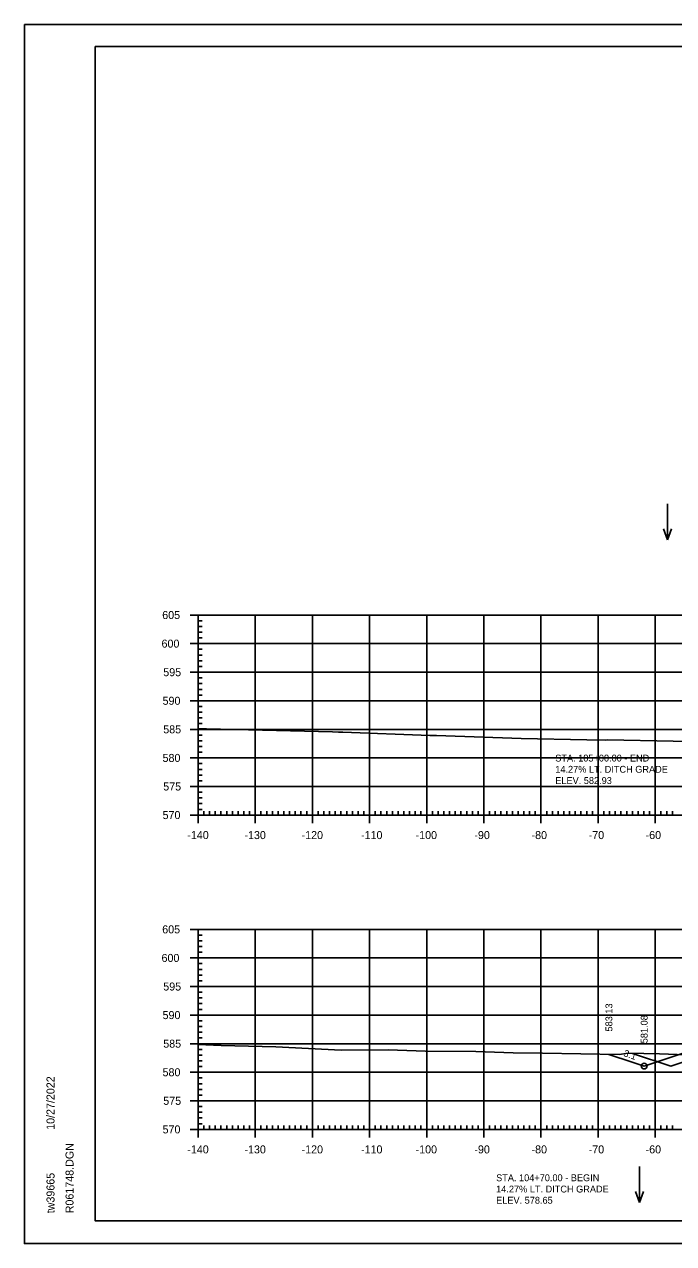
# Model space of a CAD drawing. Extents: x 961436 to 1372525, y 380079 to 2027791.
# Drawn here: x 1370020.1 to 1370133.7, y 380322.4 to 380535.8 of the extents above; entities that cross this region are included whole.
import ezdxf

# ---------------------------------------------------------------- set-up
doc = ezdxf.new("R2010")
doc.units = 0
for name, color, linetype in [('R_Axis', 7, 'Continuous'), ('R_Axis Annot', 7, 'Continuous'), ('R_Exist Surface', 7, 'Continuous'), ('R_Fin Surface', 7, 'Continuous'), ('R_Fin Surface Annot', 7, 'Continuous'), ('R_Grid', 7, 'Continuous'), ('R_No Plot', 7, 'Continuous'), ('R_Water Annot', 7, 'Continuous')]:
    doc.layers.add(name, color=color, linetype=linetype)

msp = doc.modelspace()

# ---------------------------------------------------------------- linework, layer by layer
at = {"layer": 'R_Axis'}
for p, q in [((1370049.1, 380432.4), (1370051.9, 380432.4)), ((1370050.5, 380397.4), (1370050.5, 380432.4)), ((1370050.5, 380431.4), (1370051.2, 380431.4)), ((1370050.5, 380430.4), (1370051.2, 380430.4)), ((1370050.5, 380429.4), (1370051.2, 380429.4)), ((1370050.5, 380428.4), (1370051.2, 380428.4)), ((1370049.1, 380427.4), (1370051.9, 380427.4)), ((1370050.5, 380426.4), (1370051.2, 380426.4)), ((1370050.5, 380425.4), (1370051.2, 380425.4)), ((1370050.5, 380424.4), (1370051.2, 380424.4)), ((1370049.1, 380422.4), (1370051.9, 380422.4)), ((1370050.5, 380423.4), (1370051.2, 380423.4)), ((1370050.5, 380421.4), (1370051.2, 380421.4)), ((1370050.5, 380420.4), (1370051.2, 380420.4)), ((1370050.5, 380419.4), (1370051.2, 380419.4)), ((1370049.1, 380417.4), (1370051.9, 380417.4)), ((1370050.5, 380418.4), (1370051.2, 380418.4)), ((1370050.5, 380416.4), (1370051.2, 380416.4)), ((1370050.5, 380415.4), (1370051.2, 380415.4)), ((1370050.5, 380414.4), (1370051.2, 380414.4)), ((1370050.5, 380413.4), (1370051.2, 380413.4)), ((1370049.1, 380412.4), (1370051.9, 380412.4)), ((1370050.5, 380411.4), (1370051.2, 380411.4)), ((1370050.5, 380410.4), (1370051.2, 380410.4)), ((1370050.5, 380409.4), (1370051.2, 380409.4)), ((1370049.1, 380407.4), (1370051.9, 380407.4)), ((1370050.5, 380408.4), (1370051.2, 380408.4)), ((1370050.5, 380406.4), (1370051.2, 380406.4)), ((1370050.5, 380405.4), (1370051.2, 380405.4)), ((1370049.1, 380402.4), (1370051.9, 380402.4)), ((1370050.5, 380404.4), (1370051.2, 380404.4)), ((1370050.5, 380403.4), (1370051.2, 380403.4)), ((1370050.5, 380401.4), (1370051.2, 380401.4)), ((1370050.5, 380400.4), (1370051.2, 380400.4)), ((1370050.5, 380399.4), (1370051.2, 380399.4)), ((1370050.5, 380396), (1370050.5, 380398.8)), ((1370050.5, 380398.4), (1370051.2, 380398.4)), ((1370051.5, 380397.4), (1370051.5, 380398.1)), ((1370052.5, 380397.4), (1370052.5, 380398.1)), ((1370053.5, 380397.4), (1370053.5, 380398.1)), ((1370054.5, 380397.4), (1370054.5, 380398.1)), ((1370055.5, 380397.4), (1370055.5, 380398.1)), ((1370056.5, 380397.4), (1370056.5, 380398.1)), ((1370057.5, 380397.4), (1370057.5, 380398.1)), ((1370058.5, 380397.4), (1370058.5, 380398.1)), ((1370059.5, 380397.4), (1370059.5, 380398.1)), ((1370060.5, 380396), (1370060.5, 380398.8)), ((1370061.5, 380397.4), (1370061.5, 380398.1)), ((1370062.5, 380397.4), (1370062.5, 380398.1)), ((1370063.5, 380397.4), (1370063.5, 380398.1)), ((1370064.5, 380397.4), (1370064.5, 380398.1)), ((1370065.5, 380397.4), (1370065.5, 380398.1)), ((1370066.5, 380397.4), (1370066.5, 380398.1)), ((1370067.5, 380397.4), (1370067.5, 380398.1)), ((1370068.5, 380397.4), (1370068.5, 380398.1)), ((1370069.5, 380397.4), (1370069.5, 380398.1)), ((1370070.5, 380396), (1370070.5, 380398.8)), ((1370071.5, 380397.4), (1370071.5, 380398.1)), ((1370072.5, 380397.4), (1370072.5, 380398.1)), ((1370073.5, 380397.4), (1370073.5, 380398.1)), ((1370074.5, 380397.4), (1370074.5, 380398.1)), ((1370075.5, 380397.4), (1370075.5, 380398.1)), ((1370076.5, 380397.4), (1370076.5, 380398.1)), ((1370077.5, 380397.4), (1370077.5, 380398.1)), ((1370078.5, 380397.4), (1370078.5, 380398.1)), ((1370079.5, 380397.4), (1370079.5, 380398.1)), ((1370080.5, 380396), (1370080.5, 380398.8)), ((1370081.5, 380397.4), (1370081.5, 380398.1)), ((1370082.5, 380397.4), (1370082.5, 380398.1)), ((1370083.5, 380397.4), (1370083.5, 380398.1)), ((1370084.5, 380397.4), (1370084.5, 380398.1)), ((1370085.5, 380397.4), (1370085.5, 380398.1)), ((1370086.5, 380397.4), (1370086.5, 380398.1)), ((1370087.5, 380397.4), (1370087.5, 380398.1)), ((1370088.5, 380397.4), (1370088.5, 380398.1)), ((1370089.5, 380397.4), (1370089.5, 380398.1)), ((1370090.5, 380396), (1370090.5, 380398.8)), ((1370091.5, 380397.4), (1370091.5, 380398.1)), ((1370092.5, 380397.4), (1370092.5, 380398.1)), ((1370093.5, 380397.4), (1370093.5, 380398.1)), ((1370094.5, 380397.4), (1370094.5, 380398.1)), ((1370095.5, 380397.4), (1370095.5, 380398.1)), ((1370096.5, 380397.4), (1370096.5, 380398.1)), ((1370097.5, 380397.4), (1370097.5, 380398.1)), ((1370098.5, 380397.4), (1370098.5, 380398.1)), ((1370099.5, 380397.4), (1370099.5, 380398.1)), ((1370100.5, 380396), (1370100.5, 380398.8)), ((1370101.5, 380397.4), (1370101.5, 380398.1)), ((1370102.5, 380397.4), (1370102.5, 380398.1)), ((1370103.5, 380397.4), (1370103.5, 380398.1)), ((1370104.5, 380397.4), (1370104.5, 380398.1)), ((1370105.5, 380397.4), (1370105.5, 380398.1)), ((1370106.5, 380397.4), (1370106.5, 380398.1)), ((1370107.5, 380397.4), (1370107.5, 380398.1)), ((1370108.5, 380397.4), (1370108.5, 380398.1)), ((1370109.5, 380397.4), (1370109.5, 380398.1)), ((1370110.5, 380396), (1370110.5, 380398.8)), ((1370111.5, 380397.4), (1370111.5, 380398.1)), ((1370112.5, 380397.4), (1370112.5, 380398.1)), ((1370113.5, 380397.4), (1370113.5, 380398.1)), ((1370114.5, 380397.4), (1370114.5, 380398.1)), ((1370115.5, 380397.4), (1370115.5, 380398.1)), ((1370116.5, 380397.4), (1370116.5, 380398.1)), ((1370117.5, 380397.4), (1370117.5, 380398.1)), ((1370118.5, 380397.4), (1370118.5, 380398.1)), ((1370119.5, 380397.4), (1370119.5, 380398.1)), ((1370120.5, 380396), (1370120.5, 380398.8)), ((1370121.5, 380397.4), (1370121.5, 380398.1)), ((1370122.5, 380397.4), (1370122.5, 380398.1)), ((1370123.5, 380397.4), (1370123.5, 380398.1)), ((1370124.5, 380397.4), (1370124.5, 380398.1)), ((1370125.5, 380397.4), (1370125.5, 380398.1)), ((1370126.5, 380397.4), (1370126.5, 380398.1)), ((1370127.5, 380397.4), (1370127.5, 380398.1)), ((1370128.5, 380397.4), (1370128.5, 380398.1)), ((1370129.5, 380397.4), (1370129.5, 380398.1)), ((1370130.5, 380396), (1370130.5, 380398.8)), ((1370131.5, 380397.4), (1370131.5, 380398.1)), ((1370132.5, 380397.4), (1370132.5, 380398.1)), ((1370133.5, 380397.4), (1370133.5, 380398.1)), ((1370049.1, 380397.4), (1370051.9, 380397.4)), ((1370050.5, 380397.4), (1370330.5, 380397.4)), ((1370049.1, 380377.4), (1370051.9, 380377.4)), ((1370050.5, 380342.4), (1370050.5, 380377.4)), ((1370050.5, 380376.4), (1370051.2, 380376.4)), ((1370050.5, 380375.4), (1370051.2, 380375.4)), ((1370050.5, 380374.4), (1370051.2, 380374.4)), ((1370050.5, 380373.4), (1370051.2, 380373.4)), ((1370049.1, 380372.4), (1370051.9, 380372.4)), ((1370050.5, 380371.4), (1370051.2, 380371.4)), ((1370050.5, 380370.4), (1370051.2, 380370.4)), ((1370050.5, 380369.4), (1370051.2, 380369.4)), ((1370050.5, 380368.4), (1370051.2, 380368.4)), ((1370049.1, 380367.4), (1370051.9, 380367.4)), ((1370050.5, 380366.4), (1370051.2, 380366.4)), ((1370050.5, 380365.4), (1370051.2, 380365.4)), ((1370050.5, 380364.4), (1370051.2, 380364.4)), ((1370049.1, 380362.4), (1370051.9, 380362.4)), ((1370050.5, 380363.4), (1370051.2, 380363.4)), ((1370050.5, 380361.4), (1370051.2, 380361.4)), ((1370050.5, 380360.4), (1370051.2, 380360.4)), ((1370050.5, 380359.4), (1370051.2, 380359.4)), ((1370050.5, 380358.4), (1370051.2, 380358.4)), ((1370049.1, 380357.4), (1370051.9, 380357.4)), ((1370050.5, 380356.4), (1370051.2, 380356.4)), ((1370050.5, 380355.4), (1370051.2, 380355.4)), ((1370050.5, 380354.4), (1370051.2, 380354.4)), ((1370050.5, 380353.4), (1370051.2, 380353.4)), ((1370049.1, 380352.4), (1370051.9, 380352.4)), ((1370050.5, 380351.4), (1370051.2, 380351.4)), ((1370050.5, 380350.4), (1370051.2, 380350.4)), ((1370050.5, 380349.4), (1370051.2, 380349.4)), ((1370049.1, 380347.4), (1370051.9, 380347.4)), ((1370050.5, 380348.4), (1370051.2, 380348.4)), ((1370050.5, 380346.4), (1370051.2, 380346.4)), ((1370050.5, 380345.4), (1370051.2, 380345.4)), ((1370050.5, 380344.4), (1370051.2, 380344.4)), ((1370050.5, 380341), (1370050.5, 380343.8)), ((1370050.5, 380343.4), (1370051.2, 380343.4)), ((1370051.5, 380342.4), (1370051.5, 380343.1)), ((1370052.5, 380342.4), (1370052.5, 380343.1)), ((1370053.5, 380342.4), (1370053.5, 380343.1)), ((1370054.5, 380342.4), (1370054.5, 380343.1)), ((1370055.5, 380342.4), (1370055.5, 380343.1)), ((1370056.5, 380342.4), (1370056.5, 380343.1)), ((1370057.5, 380342.4), (1370057.5, 380343.1)), ((1370058.5, 380342.4), (1370058.5, 380343.1)), ((1370059.5, 380342.4), (1370059.5, 380343.1)), ((1370060.5, 380341), (1370060.5, 380343.8)), ((1370061.5, 380342.4), (1370061.5, 380343.1)), ((1370062.5, 380342.4), (1370062.5, 380343.1)), ((1370063.5, 380342.4), (1370063.5, 380343.1)), ((1370064.5, 380342.4), (1370064.5, 380343.1)), ((1370065.5, 380342.4), (1370065.5, 380343.1)), ((1370066.5, 380342.4), (1370066.5, 380343.1)), ((1370067.5, 380342.4), (1370067.5, 380343.1)), ((1370068.5, 380342.4), (1370068.5, 380343.1)), ((1370069.5, 380342.4), (1370069.5, 380343.1)), ((1370070.5, 380341), (1370070.5, 380343.8)), ((1370071.5, 380342.4), (1370071.5, 380343.1)), ((1370072.5, 380342.4), (1370072.5, 380343.1)), ((1370073.5, 380342.4), (1370073.5, 380343.1)), ((1370074.5, 380342.4), (1370074.5, 380343.1)), ((1370075.5, 380342.4), (1370075.5, 380343.1)), ((1370076.5, 380342.4), (1370076.5, 380343.1)), ((1370077.5, 380342.4), (1370077.5, 380343.1)), ((1370078.5, 380342.4), (1370078.5, 380343.1)), ((1370079.5, 380342.4), (1370079.5, 380343.1)), ((1370080.5, 380341), (1370080.5, 380343.8)), ((1370081.5, 380342.4), (1370081.5, 380343.1)), ((1370082.5, 380342.4), (1370082.5, 380343.1)), ((1370083.5, 380342.4), (1370083.5, 380343.1)), ((1370084.5, 380342.4), (1370084.5, 380343.1)), ((1370085.5, 380342.4), (1370085.5, 380343.1)), ((1370086.5, 380342.4), (1370086.5, 380343.1)), ((1370087.5, 380342.4), (1370087.5, 380343.1)), ((1370088.5, 380342.4), (1370088.5, 380343.1)), ((1370089.5, 380342.4), (1370089.5, 380343.1)), ((1370090.5, 380341), (1370090.5, 380343.8)), ((1370091.5, 380342.4), (1370091.5, 380343.1)), ((1370092.5, 380342.4), (1370092.5, 380343.1)), ((1370093.5, 380342.4), (1370093.5, 380343.1)), ((1370094.5, 380342.4), (1370094.5, 380343.1)), ((1370095.5, 380342.4), (1370095.5, 380343.1)), ((1370096.5, 380342.4), (1370096.5, 380343.1)), ((1370097.5, 380342.4), (1370097.5, 380343.1)), ((1370098.5, 380342.4), (1370098.5, 380343.1)), ((1370099.5, 380342.4), (1370099.5, 380343.1)), ((1370100.5, 380341), (1370100.5, 380343.8)), ((1370101.5, 380342.4), (1370101.5, 380343.1)), ((1370102.5, 380342.4), (1370102.5, 380343.1)), ((1370103.5, 380342.4), (1370103.5, 380343.1)), ((1370104.5, 380342.4), (1370104.5, 380343.1)), ((1370105.5, 380342.4), (1370105.5, 380343.1)), ((1370106.5, 380342.4), (1370106.5, 380343.1)), ((1370107.5, 380342.4), (1370107.5, 380343.1)), ((1370108.5, 380342.4), (1370108.5, 380343.1)), ((1370109.5, 380342.4), (1370109.5, 380343.1)), ((1370110.5, 380341), (1370110.5, 380343.8)), ((1370111.5, 380342.4), (1370111.5, 380343.1)), ((1370112.5, 380342.4), (1370112.5, 380343.1)), ((1370113.5, 380342.4), (1370113.5, 380343.1)), ((1370114.5, 380342.4), (1370114.5, 380343.1)), ((1370115.5, 380342.4), (1370115.5, 380343.1)), ((1370116.5, 380342.4), (1370116.5, 380343.1)), ((1370117.5, 380342.4), (1370117.5, 380343.1)), ((1370118.5, 380342.4), (1370118.5, 380343.1)), ((1370119.5, 380342.4), (1370119.5, 380343.1)), ((1370120.5, 380341), (1370120.5, 380343.8)), ((1370121.5, 380342.4), (1370121.5, 380343.1)), ((1370122.5, 380342.4), (1370122.5, 380343.1)), ((1370123.5, 380342.4), (1370123.5, 380343.1)), ((1370124.5, 380342.4), (1370124.5, 380343.1)), ((1370125.5, 380342.4), (1370125.5, 380343.1)), ((1370126.5, 380342.4), (1370126.5, 380343.1)), ((1370127.5, 380342.4), (1370127.5, 380343.1)), ((1370128.5, 380342.4), (1370128.5, 380343.1)), ((1370129.5, 380342.4), (1370129.5, 380343.1)), ((1370130.5, 380341), (1370130.5, 380343.8)), ((1370131.5, 380342.4), (1370131.5, 380343.1)), ((1370132.5, 380342.4), (1370132.5, 380343.1)), ((1370133.5, 380342.4), (1370133.5, 380343.1)), ((1370049.1, 380342.4), (1370051.9, 380342.4)), ((1370050.5, 380342.4), (1370330.5, 380342.4))]:
    msp.add_line(p, q, dxfattribs=at)
at = {"layer": 'R_Exist Surface'}
for points in [[(1370050.5, 380412.52), (1370051.96, 380412.47), (1370074.02, 380411.94), (1370075.05, 380411.88), (1370075.81, 380411.89), (1370091.04, 380411.32), (1370092.22, 380411.32), (1370107.01, 380410.78), (1370118.53, 380410.55), (1370121.76, 380410.5), (1370122.16, 380410.55), (1370133.63, 380410.34), (1370143.09, 380410)], [(1370050.5, 380357.24), (1370054.53, 380357.1), (1370064.12, 380356.87), (1370075.54, 380356.24), (1370083.74, 380356.35), (1370090.28, 380356.11), (1370099.11, 380356.05), (1370105.61, 380355.82), (1370110.77, 380355.71), (1370124.16, 380355.5), (1370125.78, 380355.71), (1370131.22, 380355.61), (1370145.24, 380355.1)]]:
    msp.add_lwpolyline(points, dxfattribs=at)
at = {"layer": 'R_Fin Surface'}
for points in [[(1370122.39, 380355.53), (1370126.48, 380354.17), (1370128.56, 380353.47), (1370142.27, 380358.04), (1370154.59, 380362.15), (1370163.27, 380365.04), (1370171.03, 380367.63), (1370174, 380368.62), (1370181.5, 380368.92), (1370190.5, 380369.1), (1370199.5, 380368.92), (1370207, 380368.62), (1370209.77, 380367.7), (1370217.76, 380365.03), (1370228.55, 380361.43), (1370250.85, 380354), (1370252.08, 380353.59), (1370253.6, 380353.09), (1370254.86, 380352.67), (1370255.61, 380352.42)], [(1370126.5, 380355.7), (1370133.2, 380353.47), (1370171.5, 380366.24), (1370176.17, 380367.79), (1370179.5, 380368.9), (1370181.5, 380368.98), (1370190.5, 380369.16), (1370199.5, 380368.98), (1370201.5, 380368.9), (1370204.84, 380367.79), (1370209.5, 380366.24), (1370246.19, 380354), (1370250.15, 380352.69)]]:
    msp.add_lwpolyline(points, dxfattribs=at)
at = {"layer": 'R_Grid'}
for p, q in [((1370050.5, 380432.4), (1370330.5, 380432.4)), ((1370050.5, 380397.4), (1370050.5, 380432.4)), ((1370060.5, 380397.4), (1370060.5, 380432.4)), ((1370070.5, 380397.4), (1370070.5, 380432.4)), ((1370080.5, 380397.4), (1370080.5, 380432.4)), ((1370090.5, 380397.4), (1370090.5, 380432.4)), ((1370100.5, 380397.4), (1370100.5, 380432.4)), ((1370110.5, 380397.4), (1370110.5, 380432.4)), ((1370120.5, 380397.4), (1370120.5, 380432.4)), ((1370130.5, 380397.4), (1370130.5, 380432.4)), ((1370050.5, 380427.4), (1370330.5, 380427.4)), ((1370050.5, 380422.4), (1370330.5, 380422.4)), ((1370050.5, 380417.4), (1370330.5, 380417.4)), ((1370050.5, 380412.4), (1370330.5, 380412.4)), ((1370050.5, 380407.4), (1370330.5, 380407.4)), ((1370050.5, 380402.4), (1370330.5, 380402.4)), ((1370050.5, 380397.4), (1370330.5, 380397.4)), ((1370050.5, 380377.4), (1370330.5, 380377.4)), ((1370050.5, 380342.4), (1370050.5, 380377.4)), ((1370060.5, 380342.4), (1370060.5, 380377.4)), ((1370070.5, 380342.4), (1370070.5, 380377.4)), ((1370080.5, 380342.4), (1370080.5, 380377.4)), ((1370090.5, 380342.4), (1370090.5, 380377.4)), ((1370100.5, 380342.4), (1370100.5, 380377.4)), ((1370110.5, 380342.4), (1370110.5, 380377.4)), ((1370120.5, 380342.4), (1370120.5, 380377.4)), ((1370130.5, 380342.4), (1370130.5, 380377.4)), ((1370050.5, 380372.4), (1370330.5, 380372.4)), ((1370050.5, 380367.4), (1370330.5, 380367.4)), ((1370050.5, 380362.4), (1370330.5, 380362.4)), ((1370050.5, 380357.4), (1370330.5, 380357.4)), ((1370050.5, 380352.4), (1370330.5, 380352.4)), ((1370050.5, 380347.4), (1370330.5, 380347.4)), ((1370050.5, 380342.4), (1370330.5, 380342.4))]:
    msp.add_line(p, q, dxfattribs=at)
at = {"layer": 'R_No Plot'}
for p, q in [((1370020.1, 380535.75), (1370353.44, 380535.75)), ((1370032.5, 380531.86), (1370348.68, 380531.86)), ((1370032.5, 380326.4), (1370032.5, 380531.86)), ((1370032.5, 380326.4), (1370032.5, 380326.4)), ((1370348.68, 380326.4), (1370032.5, 380326.4)), ((1370020.1, 380322.42), (1370353.44, 380322.42))]:
    msp.add_line(p, q, dxfattribs=at)
for points in [[(1370020.1, 380535.75), (1370353.44, 380535.75), (1370353.44, 380322.41), (1370020.1, 380322.41)], [(1370266.42, 380531.86), (1370286.04, 380531.86), (1370286.04, 380521.98), (1370302.16, 380521.98), (1370325.36, 380521.98), (1370325.48, 380493.82), (1370348.68, 380493.82), (1370348.68, 380326.4), (1370032.5, 380326.4), (1370032.5, 380531.86)]]:
    msp.add_lwpolyline(points, close=True, dxfattribs=at)
msp.add_circle((1370128.56, 380353.47), 0.5, dxfattribs=at)
at = {"layer": 'R_Water Annot'}
for p, q in [((1370132.62, 380451.86), (1370132.62, 380445.58)), ((1370132.62, 380445.58), (1370131.92, 380447.5)), ((1370132.62, 380445.58), (1370133.32, 380447.5)), ((1370127.74, 380335.9), (1370127.74, 380329.61)), ((1370127.74, 380329.61), (1370127.04, 380331.54)), ((1370127.74, 380329.61), (1370128.44, 380331.54))]:
    msp.add_line(p, q, dxfattribs=at)

# ---------------------------------------------------------------- texts
at = {"layer": 'R_Axis Annot'}
for s, p in [('605', (1370044.22, 380431.7)), ('600', (1370044.1, 380426.7)), ('595', (1370044.4, 380421.7)), ('590', (1370044.28, 380416.7)), ('585', (1370044.4, 380411.7)), ('580', (1370044.28, 380406.7)), ('575', (1370044.4, 380401.7)), ('570', (1370044.28, 380396.7)), ('-140', (1370048.61, 380393.2)), ('-130', (1370058.61, 380393.2)), ('-120', (1370068.61, 380393.2)), ('-110', (1370079.01, 380393.2)), ('-100', (1370088.56, 380393.2)), ('-90', (1370098.85, 380393.2)), ('-80', (1370108.85, 380393.2)), ('-70', (1370118.85, 380393.2)), ('-60', (1370128.81, 380393.2)), ('605', (1370044.22, 380376.7)), ('600', (1370044.1, 380371.7)), ('595', (1370044.4, 380366.7)), ('590', (1370044.28, 380361.7)), ('585', (1370044.4, 380356.7)), ('580', (1370044.28, 380351.7)), ('575', (1370044.4, 380346.7)), ('570', (1370044.28, 380341.7)), ('-140', (1370048.61, 380338.2)), ('-130', (1370058.61, 380338.2)), ('-120', (1370068.61, 380338.2)), ('-110', (1370079.01, 380338.2)), ('-100', (1370088.56, 380338.2)), ('-90', (1370098.85, 380338.2)), ('-80', (1370108.85, 380338.2)), ('-70', (1370118.85, 380338.2)), ('-60', (1370128.81, 380338.2))]:
    msp.add_text(s, height=1.4, dxfattribs=at).set_placement(p)
at = {"layer": 'R_Fin Surface Annot'}
for s, p in [('STA. 105+00.00 - END', (1370113, 380406.77)), ('14.27% LT. DITCH GRADE', (1370113, 380404.81)), ('ELEV. 582.93', (1370113, 380402.84)), ('STA. 104+70.00 - BEGIN', (1370102.65, 380333.33)), ('14.27% LT. DITCH GRADE', (1370102.65, 380331.36)), ('ELEV. 578.65', (1370102.65, 380329.4))]:
    msp.add_text(s, height=1.2, dxfattribs=at).set_placement(p)
for s, rotation, p in [('583.13', 90, (1370122.99, 380359.53)), ('581.08', 90, (1370129.16, 380357.47)), ('3:1', 341.5651, (1370124.85, 380355.24))]:
    msp.add_text(s, height=1.2, rotation=rotation, dxfattribs=at).set_placement(p)
at = {"layer": 'R_No Plot'}
for s, p in [('10/27/2022', (1370025.37, 380342.32)), ('R061748.DGN', (1370028.7, 380327.72)), ('tw39665', (1370025.37, 380327.72))]:
    msp.add_text(s, height=1.4, rotation=90, dxfattribs=at).set_placement(p)

doc.saveas('drawing.dxf')
